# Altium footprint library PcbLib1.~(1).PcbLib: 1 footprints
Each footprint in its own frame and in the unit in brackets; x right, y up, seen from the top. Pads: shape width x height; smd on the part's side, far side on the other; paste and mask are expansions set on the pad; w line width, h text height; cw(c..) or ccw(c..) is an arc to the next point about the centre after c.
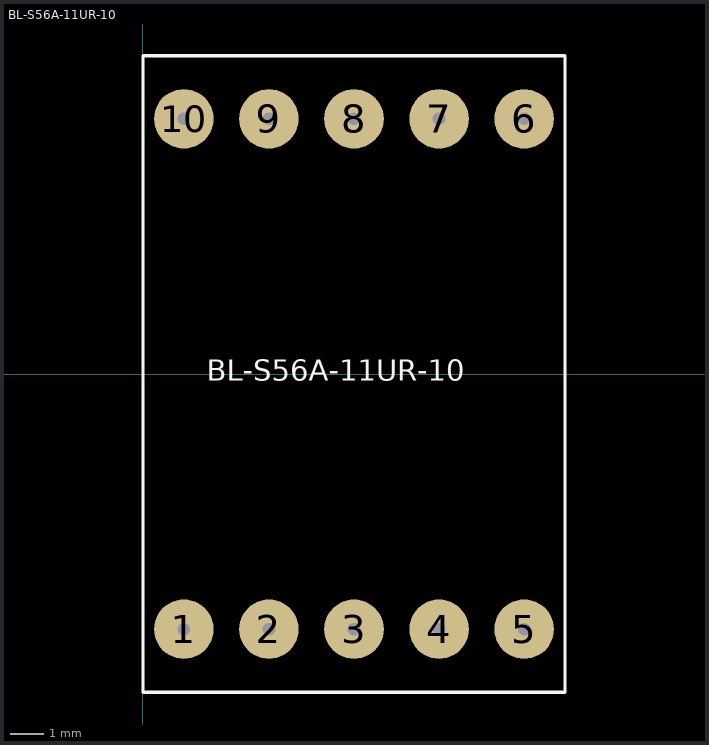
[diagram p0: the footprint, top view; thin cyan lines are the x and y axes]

## BL-S56A-11UR-10 [mil]
pads (10):
  round 70 hole 15: 1(48.03,-300) 2(148.03,-300) 3(248.03,-300) 4(348.03,-300) 5(448.03,-300) 6(448.03,300) 7(348.03,300) 8(248.03,300) 9(148.03,300) 10(48.03,300)
Top Overlay:
  lines w3.94: 496.06,122.05 496.06,374.02 ; 496.06,374.02 0,374.02 0,-374.02 496.06,-374.02 496.06,374.02
  text "BL-S56A-11UR-10" at 75,-8 h25
3D body: height 314.96, standoff 0, extent 0,-374.02 496.06,374.02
